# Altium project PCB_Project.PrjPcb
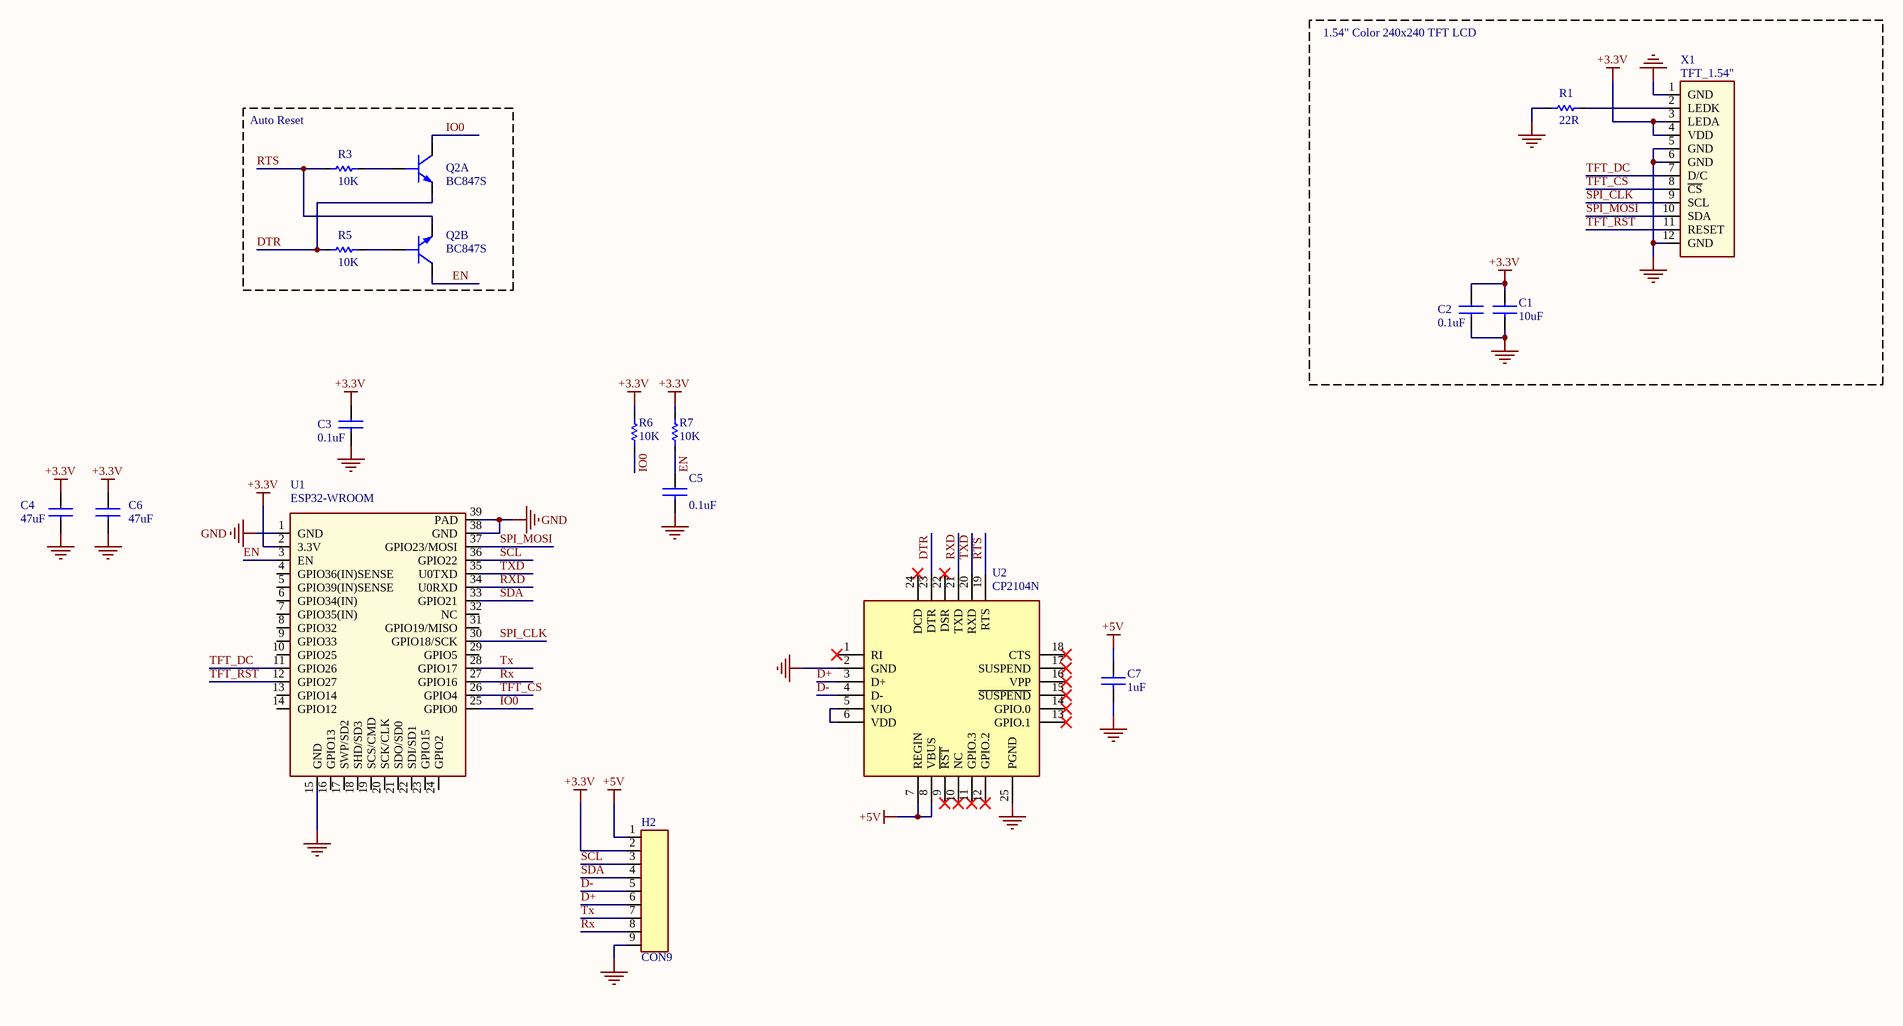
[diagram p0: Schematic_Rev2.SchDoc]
1 sheet, 17 parts. Net scope: global (net labels, ports and power ports of the same name join across sheets).
Board file: PCB_Rev2.PcbDoc

## Sheet Schematic_Rev2.SchDoc: ESP32 Particle Sensor, Display
size Tabloid; CompanyName: z; DrawnBy: @mikerankin; Engineer: x; Organization: .; Address1: @mikerankin; Address2: .; Address3: .; Address4: .; DocumentNumber: .; Revision: 2; SheetNumber: 1; SheetTotal: 1

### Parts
C1  10uF  [CAPC2012X140N]
C2  0.1uF  [CAPC1005X56N]
C3  0.1uF  [CAPC1005X56N]
C4  47uF  [CAPC3225X160N]
C5  0.1uF  [CAPC1005X56N]
C6  47uF  [CAPC3225X160N]
C7  1uF  [CAPC1005X56N]
H2  CON9  [HDR9X1-50MIL]  (no BOM)
Q2  BC847S  [SOT65P210X110-6N]  (parts A,B of 2)
R1  22R  [RESC1005X40L (0402 FOOTPRINT)]
R3  10K  [RESC1005X40L (0402 FOOTPRINT)]
R5  10K  [RESC1005X40L (0402 FOOTPRINT)]
R6  10K  [RESC1005X40L (0402 FOOTPRINT)]
R7  10K  [RESC1005X40L (0402 FOOTPRINT)]
U1  ESP32-WROOM  [ESP32]
U2  CP2104N  [24-QFN]
X1  TFT_1.54"  [TFT_GLASS 1.54 INCH]

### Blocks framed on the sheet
1.54" Color 240x240 TFT LCD: C1 C2 R1 X1
Auto Reset: Q2 R3 R5

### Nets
+3.3V: C1.1 C2.1 C3.1 C4.1 C6.1 H2.2 R6.1 R7.1 U1.2(3.3V) X1.3(LEDA) X1.4(VDD)
+5V: C7.1 H2.1 U2.7(REGIN) U2.8(VBUS)
GND: C1.2 C2.2 C3.2 C4.2 C5.2 C6.2 C7.2 H2.9 R1.2 U1.1(GND) U1.15(GND) U1.38(GND) U1.39(PAD) U2.2(GND) U2.25(PGND) X1.1(GND) X1.5(GND) X1.6(GND) X1.12(GND)
D+: H2.6 U2.3(D+)
D-: H2.5 U2.4(D-)
DTR: Q2.1(E1) R5.2 U2.23(DTR)
EN: C5.1 Q2.3(C2) R7.2 U1.3(EN)
IO0: Q2.6(C1) R6.2 U1.25(GPIO0)
RTS: Q2.4(E2) R3.2 U2.19(RTS)
Rx: H2.8 U1.27(GPIO16)
RXD: U1.34(U0RXD) U2.21(TXD)
SCL: H2.3 U1.36(GPIO22)
SDA: H2.4 U1.33(GPIO21)
SPI_CLK: U1.30(GPIO18/SCK) X1.9(SCL)
SPI_MOSI: U1.37(GPIO23/MOSI) X1.10(SDA)
TFT_CS: U1.26(GPIO4) X1.8(~{CS})
TFT_DC: U1.11(GPIO26) X1.7(D/C)
TFT_RST: U1.12(GPIO27) X1.11(RESET)
Tx: H2.7 U1.28(GPIO17)
TXD: U1.35(U0TXD) U2.20(RXD)
NetQ2_2: Q2.2(B1) R3.1
NetQ2_5: Q2.5(B2) R5.1
NetR1_1: R1.1 X1.2(LEDK)
NetU2_5: U2.5(VIO) U2.6(VDD)

Not connected (* = marked no-connect by the designer): U1 4(GPIO36(IN)SENSE) 5(GPIO39(IN)SENSE) 6(GPIO34(IN)) 7(GPIO35(IN)) 8(GPIO32) 9(GPIO33) 10(GPIO25) 13(GPIO14) 14(GPIO12) 16(GPIO13) 17(SWP/SD2) 18(SHD/SD3) 19(SCS/CMD) 20(SCK/CLK) 21(SDO/SD0) 22(SDI/SD1) 23(GPIO15) 24(GPIO2) 29(GPIO5) 31(GPIO19/MISO) 32(NC); U2 1(RI)* 9(~{RST})* 10(NC)* 11(GPIO.3)* 12(GPIO.2)* 13(GPIO.1)* 14(GPIO.0)* 15(~{SUSPEND})* 16(VPP)* 17(SUSPEND)* 18(CTS)* 22(DSR)* 24(DCD)*

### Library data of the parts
C1 = CAP_0805: CAP 10uF 0805; Manufacturer: Samsung; Part_Footprint: 0805; Part_Number: C307520; Vendor: LCSC
C2 C3 C5 = CAP_0402: CAP 0.1uF 0402; Part_Number: C60474; Manufacturer: Yageo; Part_Footprint: 0402; Vendor: LCSC
C4 C6 = CAP_1210: CAP 47uF 1210; Part_Number: C77101; Manufacturer: Murata; Part_Footprint: 1210; Vendor: LCSC
C7 = CAP_0603: CAP 1uF 16V 0402; Part_Footprint: 0402; Manufacturer: Walsin; Part_Number: C83063; Vendor: LCSC
H2 = CON9: CONN HEADER 9POS .100" PADS
Q2 = BC847S: TRANS 2NPN 44V 0.1A SC-70-6; Manufacturer: Changjiang; Part_Number: C148112; Vendor: LCSC
R1 = RES_0402: RES 22R 0402; Part_Footprint: C25092; Manufacturer: Uniroyal; Vendor: LCSC
R3 R5 = RES_0402: RES 10K 0402; Manufacturer: Guangdong; Part_Number: C258091; Part_Footprint: 0402; Vendor: LCSC
R6 R7 = RES_0402: RES 10K 0402; Part_Footprint: 0402; Manufacturer: Guangdong; Part_Number: C258091; Vendor: LCSC
U1 = ESP32: WIFI/Bluetooth, SMD Module; Manufacturer: Espressif; Part_Number: ESP32-WROOM-32D-N4; Vendor: Digi-Key
U2 = CP2104N: IC BRIDGE USB TO UART 24QFN; Manufacturer: Silicon Labs; Part_Number: C47742; Vendor: LCSC
X1 = TFT_GLASS 1.54 INCH COLOR: 1.54 INCH TFT GLASS COLOR; Part_Number: ER-TFT1.54-1; Manufacturer: BuyDisplay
